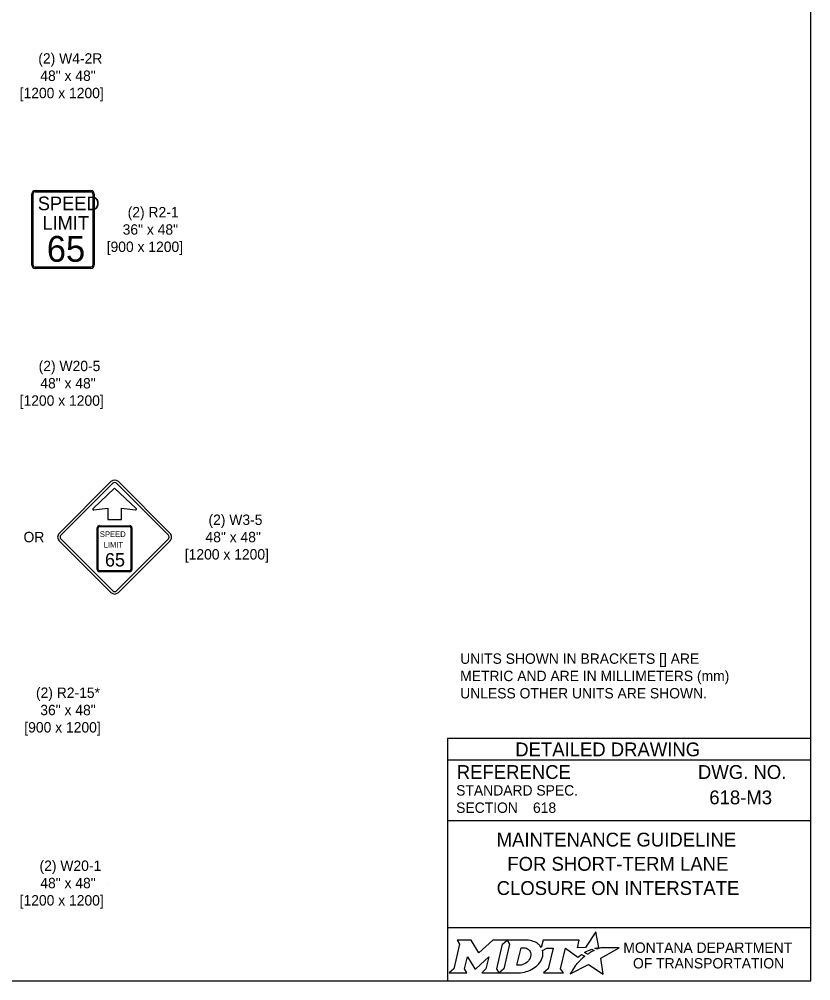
# Model space of a CAD drawing. Extents: x 49991.4 to 50021, y 49987.6 to 50011.4.
# Drawn here: x 50004.04 to 50008.61, y 50000.06 to 50005.62 of the extents above; entities that cross this region are included whole.
import ezdxf

# ---------------------------------------------------------------- set-up
doc = ezdxf.new("R2010")
doc.units = 0
doc.layers.add('Level 1', color=7, linetype='Continuous')
doc.layers.add('Level 2', color=7, linetype='Continuous')

msp = doc.modelspace()

# ---------------------------------------------------------------- linework, layer by layer
at = {"layer": 'Level 1'}
for p, q in [((50004.1301, 50004.6303), (50004.4527, 50004.6303)), ((50004.1114, 50004.1991), (50004.1114, 50004.6115)), ((50004.1189, 50004.1991), (50004.1189, 50004.6115)), ((50004.1301, 50004.6228), (50004.4527, 50004.6228)), ((50004.4639, 50004.6115), (50004.4639, 50004.1991)), ((50004.4714, 50004.6115), (50004.4714, 50004.1991)), ((50004.4527, 50004.1878), (50004.1301, 50004.1878)), ((50004.4527, 50004.1803), (50004.1301, 50004.1803)), ((50004.5691, 50002.9481), (50004.2698, 50002.6488)), ((50004.5792, 50002.938), (50004.2799, 50002.6387)), ((50004.5905, 50002.9097), (50004.4661, 50002.7924)), ((50004.5691, 50002.9481), (50004.5691, 50002.9481)), ((50004.5792, 50002.938), (50004.5792, 50002.938)), ((50004.7149, 50002.7924), (50004.5905, 50002.9097)), ((50004.9011, 50002.6387), (50004.6018, 50002.938)), ((50004.9112, 50002.6488), (50004.6119, 50002.9481)), ((50004.4702, 50002.7837), (50004.5502, 50002.7937)), ((50004.5502, 50002.7937), (50004.5502, 50002.7282)), ((50004.6308, 50002.7282), (50004.6308, 50002.7937)), ((50004.6308, 50002.7937), (50004.7108, 50002.7837)), ((50004.5026, 50002.6931), (50004.6774, 50002.6931)), ((50004.5026, 50002.6879), (50004.6774, 50002.6879)), ((50004.5502, 50002.7282), (50004.6308, 50002.7282)), ((50004.59, 50002.6931), (50004.59, 50002.6931)), ((50004.4901, 50002.4394), (50004.4901, 50002.6807)), ((50004.4953, 50002.4394), (50004.4953, 50002.6807)), ((50004.6846, 50002.6807), (50004.6846, 50002.4394)), ((50004.6898, 50002.6807), (50004.6898, 50002.4394)), ((50004.2698, 50002.606), (50004.5691, 50002.3067)), ((50004.2799, 50002.6161), (50004.5792, 50002.3168)), ((50004.6018, 50002.3168), (50004.9011, 50002.6161)), ((50004.6119, 50002.3067), (50004.9112, 50002.606)), ((50004.6774, 50002.4321), (50004.5026, 50002.4321)), ((50004.6774, 50002.4269), (50004.5026, 50002.4269))]:
    msp.add_line(p, q, dxfattribs=at)
msp.add_lwpolyline([(50008.6146, 50011.2628), (50000.3356, 50011.2628), (50000.3356, 50000.0624), (50008.6146, 50000.0624)], close=True, dxfattribs=at)
for centre, radius, start, end in [((50004.1301, 50004.6115), 0.0187, 90, 180), ((50004.4526, 50004.6115), 0.0187, 0, 90), ((50004.1301, 50004.6115), 0.0113, 90, 180), ((50004.4526, 50004.6115), 0.0113, 0, 90), ((50004.1301, 50004.199), 0.0187, 180, 270), ((50004.1301, 50004.199), 0.0113, 180, 270), ((50004.4526, 50004.199), 0.0187, 270, 0), ((50004.4526, 50004.199), 0.0113, 270, 0), ((50004.5905, 50002.9267), 0.0302, 45.0001, 134.9999), ((50004.5905, 50002.9267), 0.016, 45.0001, 134.9999), ((50004.4696, 50002.7887), 0.00508, 134.6287, 275.8295), ((50004.7113, 50002.7888), 0.00509, 264.3826, 45.1649), ((50004.5026, 50002.6807), 0.0125, 90, 180), ((50004.5026, 50002.6807), 0.00728, 90, 180), ((50004.6774, 50002.6807), 0.0125, 360, 90), ((50004.6774, 50002.6807), 0.00728, 360, 90), ((50004.2912, 50002.6274), 0.0302, 134.9999, 225.0001), ((50004.2912, 50002.6274), 0.016, 134.9999, 225.0001), ((50004.8898, 50002.6274), 0.016, 314.9999, 45.0001), ((50004.8898, 50002.6274), 0.0302, 314.9999, 45.0001), ((50004.5026, 50002.4394), 0.0125, 180, 270), ((50004.5026, 50002.4394), 0.00728, 180, 270), ((50004.6774, 50002.4394), 0.00728, 270, 360), ((50004.6774, 50002.4394), 0.0125, 270, 360), ((50004.5905, 50002.3281), 0.0302, 225.0001, 314.9999), ((50004.5905, 50002.3281), 0.016, 225.0001, 314.9999)]:
    msp.add_arc(centre, radius, start, end, dxfattribs=at)
at = {"layer": 'Level 2'}
for p, q in [((50008.6146, 50001.4624), (50006.5146, 50001.4624)), ((50006.5146, 50001.4624), (50006.5146, 50000.0624)), ((50008.6146, 50001.3374), (50006.5146, 50001.3374)), ((50008.2507, 50001.1223), (50008.2507, 50001.1223)), ((50007.0089, 50001.0629), (50007.0089, 50001.0629)), ((50008.6146, 50000.9874), (50006.5146, 50000.9874)), ((50007.5646, 50000.7383), (50007.5646, 50000.7383)), ((50004.554, 50000.6274), (50004.554, 50000.6274)), ((50008.6146, 50000.3693), (50006.5146, 50000.3693))]:
    msp.add_line(p, q, dxfattribs=at)
for points in [[(50006.5701, 50000.2974), (50006.5842, 50000.274), (50006.5507, 50000.1307), (50006.525, 50000.1082), (50006.6266, 50000.1082), (50006.6131, 50000.131), (50006.6293, 50000.2011), (50006.673, 50000.1321), (50006.6783, 50000.1321), (50006.7534, 50000.2016), (50006.737, 50000.1305), (50006.7123, 50000.1085), (50006.8139, 50000.1085), (50006.8001, 50000.1318), (50006.8333, 50000.2742)], [(50006.8333, 50000.2742), (50006.8586, 50000.2974), (50006.7762, 50000.2974), (50006.6966, 50000.2244), (50006.6521, 50000.2971), (50006.5701, 50000.2974)], [(50006.9722, 50000.2974), (50006.8586, 50000.2974), (50006.8733, 50000.2745), (50006.8394, 50000.1307), (50006.8139, 50000.1085), (50006.9245, 50000.1085)], [(50007.3771, 50000.2447), (50007.3668, 50000.2503), (50007.3784, 50000.2531), (50007.39, 50000.2551), (50007.3726, 50000.3452), (50007.3131, 50000.2539), (50007.2658, 50000.2532), (50007.2761, 50000.2973), (50007.0669, 50000.2974), (50007.0568, 50000.2549), (50007.051, 50000.2632)], [(50006.9962, 50000.2107), (50006.995, 50000.2026), (50006.9918, 50000.1933), (50006.9876, 50000.1851), (50006.982, 50000.1776), (50006.9755, 50000.1707), (50006.9676, 50000.1644), (50006.9593, 50000.1597), (50006.9502, 50000.1558), (50006.9411, 50000.1535), (50006.9319, 50000.1526), (50006.916, 50000.1526), (50006.9396, 50000.2526), (50006.9556, 50000.2526), (50006.9632, 50000.252), (50006.9708, 50000.2501), (50006.9774, 50000.2471), (50006.9835, 50000.2429), (50006.9883, 50000.2379), (50006.992, 50000.2319), (50006.9947, 50000.2257), (50006.9963, 50000.2183), (50006.9963, 50000.2153), (50006.9962, 50000.2107)], [(50007.0636, 50000.2383), (50007.0882, 50000.2514), (50007.1251, 50000.2514), (50007.0965, 50000.1309), (50007.069, 50000.1082), (50007.1852, 50000.1082), (50007.1682, 50000.1311), (50007.1964, 50000.2513), (50007.2677, 50000.1996), (50007.2888, 50000.2147), (50007.3085, 50000.2038)], [(50007.2527, 50000.1479), (50007.2374, 50000.1235), (50007.2327, 50000.116), (50007.2269, 50000.1074), (50007.2246, 50000.1031), (50007.3299, 50000.1562), (50007.4138, 50000.1011), (50007.4007, 50000.1938), (50007.5076, 50000.2522), (50007.4583, 50000.253), (50007.4282, 50000.2534), (50007.4074, 50000.2537), (50007.4006, 50000.2522), (50007.3957, 50000.251), (50007.3873, 50000.2487), (50007.3771, 50000.2447)], [(50007.3267, 50000.2171), (50007.3243, 50000.2154), (50007.306, 50000.225), (50007.3163, 50000.2307), (50007.3204, 50000.2329), (50007.329, 50000.2369), (50007.3347, 50000.2395), (50007.3426, 50000.2425), (50007.3499, 50000.2452), (50007.3617, 50000.2378), (50007.3577, 50000.2357), (50007.3531, 50000.2332), (50007.3489, 50000.231), (50007.3439, 50000.2281), (50007.342, 50000.227), (50007.3393, 50000.2254), (50007.3368, 50000.224), (50007.3345, 50000.2224), (50007.3319, 50000.2206), (50007.3292, 50000.2188), (50007.3267, 50000.2171)], [(50006.9702, 50000.1158), (50006.9786, 50000.1184), (50006.9916, 50000.1238), (50007.012, 50000.1348)], [(50007.2666, 50000.164), (50007.2666, 50000.164)]]:
    msp.add_lwpolyline(points, dxfattribs=at)
for centre, radius, start, end in [((50006.9513, 50000.2363), 0.1183, 300.9103, 339.1383), ((50006.9953, 50000.219), 0.0709, 339.5329, 15.8582)]:
    msp.add_arc(centre, radius, start, end, dxfattribs=at)
for centre, major_axis, ratio, start_param, end_param in [((50006.9701, 50000.25), (0.0834, -0.0037), 0.568097, 0.61298, 1.570796), ((50007.0257, 50000.2573), (0.0361, -0.0295), 0.469099, 1.225588, 1.570796), ((50007.2764, 50000.1742), (-0.0098, -0.0102), 0.016458, 3.141593, 6.279097), ((50007.2974, 50000.1941), (-0.0112, -0.0097), 0.021651, 3.157348, 6.283185), ((50007.2597, 50000.1559), (-0.00694, -0.00806), 0.008222, 0, 3.137361), ((50006.9248, 50000.2568), (0, 0.1484), 0.987302, 3.139398, 3.456847)]:
    msp.add_ellipse(centre, major_axis=major_axis, ratio=ratio, start_param=start_param, end_param=end_param, dxfattribs=at)

# ---------------------------------------------------------------- texts
at = {"layer": 'Level 1'}
for s, height, p in [('SPEED', 0.07884, (50004.1461, 50004.5166)), ('LIMIT', 0.07884, (50004.1726, 50004.404)), ('65', 0.14918, (50004.1981, 50004.2186))]:
    msp.add_text(s, height=height, dxfattribs=at).set_placement(p)
for s, height, p in [('SPEED', 0.03301, (50004.5047, 50002.6274)), ('LIMIT', 0.03301, (50004.5265, 50002.5664)), ('65', 0.07775, (50004.5345, 50002.457))]:
    msp.add_text(s, height=height, rotation=360, dxfattribs=at).set_placement(p)
at = {"layer": 'Level 2'}
for s, height, p in [('(2) W4-2R', 0.06, (50004.1491, 50005.3641)), ('48" x 48"', 0.06, (50004.1607, 50005.2641)), ('[1200 x 1200]', 0.06, (50004.0412, 50005.1641)), ('(2) R2-1', 0.06, (50004.6657, 50004.4753)), ('36" x 48"', 0.06, (50004.6368, 50004.3753)), ('[900 x 1200]', 0.06, (50004.5443, 50004.2753)), ('(2) W20-5', 0.06, (50004.1511, 50003.5863)), ('48" x 48"', 0.06, (50004.1607, 50003.4863)), ('[1200 x 1200]', 0.06, (50004.0412, 50003.3863)), ('(2) W3-5', 0.06, (50005.1328, 50002.6974)), ('OR', 0.06, (50004.0636, 50002.5974)), ('48" x 48"', 0.06, (50005.1155, 50002.5974)), ('[1200 x 1200]', 0.06, (50004.996, 50002.4974)), ('UNITS SHOWN IN BRACKETS [] ARE ', 0.06, (50006.588, 50001.8945)), ('METRIC AND ARE IN MILLIMETERS (mm) ', 0.06, (50006.588, 50001.7945)), ('(2) R2-15*', 0.06, (50004.1355, 50001.6975)), ('UNLESS OTHER UNITS ARE SHOWN.', 0.06, (50006.588, 50001.6945)), ('36" x 48"', 0.06, (50004.1607, 50001.5975)), ('[900 x 1200]', 0.06, (50004.0682, 50001.4975)), ('DETAILED DRAWING', 0.0799, (50006.9063, 50001.3599)), ('REFERENCE', 0.08, (50006.5682, 50001.229)), ('DWG. NO.', 0.08, (50007.9624, 50001.229)), ('STANDARD SPEC.', 0.06, (50006.5649, 50001.133)), ('618-M3', 0.08, (50008.0281, 50001.0823)), ('SECTION', 0.06, (50006.5649, 50001.033)), ('618', 0.06, (50007.0089, 50001.0329)), ('MAINTENANCE GUIDELINE', 0.08, (50006.7987, 50000.8383)), ('(2) W20-1', 0.06, (50004.1562, 50000.6974)), ('FOR SHORT-TERM LANE', 0.08, (50006.8603, 50000.6983)), ('48" x 48"', 0.06, (50004.1607, 50000.5974)), ('CLOSURE ON INTERSTATE', 0.08, (50006.7987, 50000.5583)), ('[1200 x 1200]', 0.06, (50004.0412, 50000.4974)), ('MONTANA DEPARTMENT', 0.06, (50007.5308, 50000.2236)), ('OF TRANSPORTATION', 0.06, (50007.587, 50000.1336))]:
    msp.add_text(s, height=height, dxfattribs=at).set_placement(p)

doc.saveas('drawing.dxf')
